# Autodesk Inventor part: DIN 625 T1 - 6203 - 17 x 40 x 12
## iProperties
Library Location: C:\Program Files\Autodesk\Inventor 6\content
Library: local
SubLibrary: DIN
Family: 249
Member: 610
Member Major Revision: 1
Member Minor Revision: 1
Comments: To add or edit properties for Autodesk Inventor files, use iProperties.
Created: 2003-05
Part Number: DIN 625 T1 - 6203 - 17 x 40 x 12
Vendor: Autodesk Inc.
Document SubType Name: Modeling
Designer: Philippe
Description: Roulement rainuré à billes
Standard: DIN 625 T1 6203 - 17 x 40 x 12
Alert: To add or edit properties for Autodesk Inventor files, use iProperties.
Control State: 0
Master: False
Checked Out: False
Shininess: 64.0
Length Units: 11269
Angle Units: 11279
Time Units: 11290
Mass Units: 11283
Length Display Precision: 3
Angle Display Precision: 2
Compacted: True
Classification: un/spsc 31171504
Density: 0.0
Volumn: 0.0
Area: 0.0
PropertySet Name: Model Information
Author: Philippe
Revision Number: 1
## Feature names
1. Corps [Revolution]
2. Congé1 [Fillet]
3. Sphère [Revolution]
4. Sphères [Circular Pattern]
